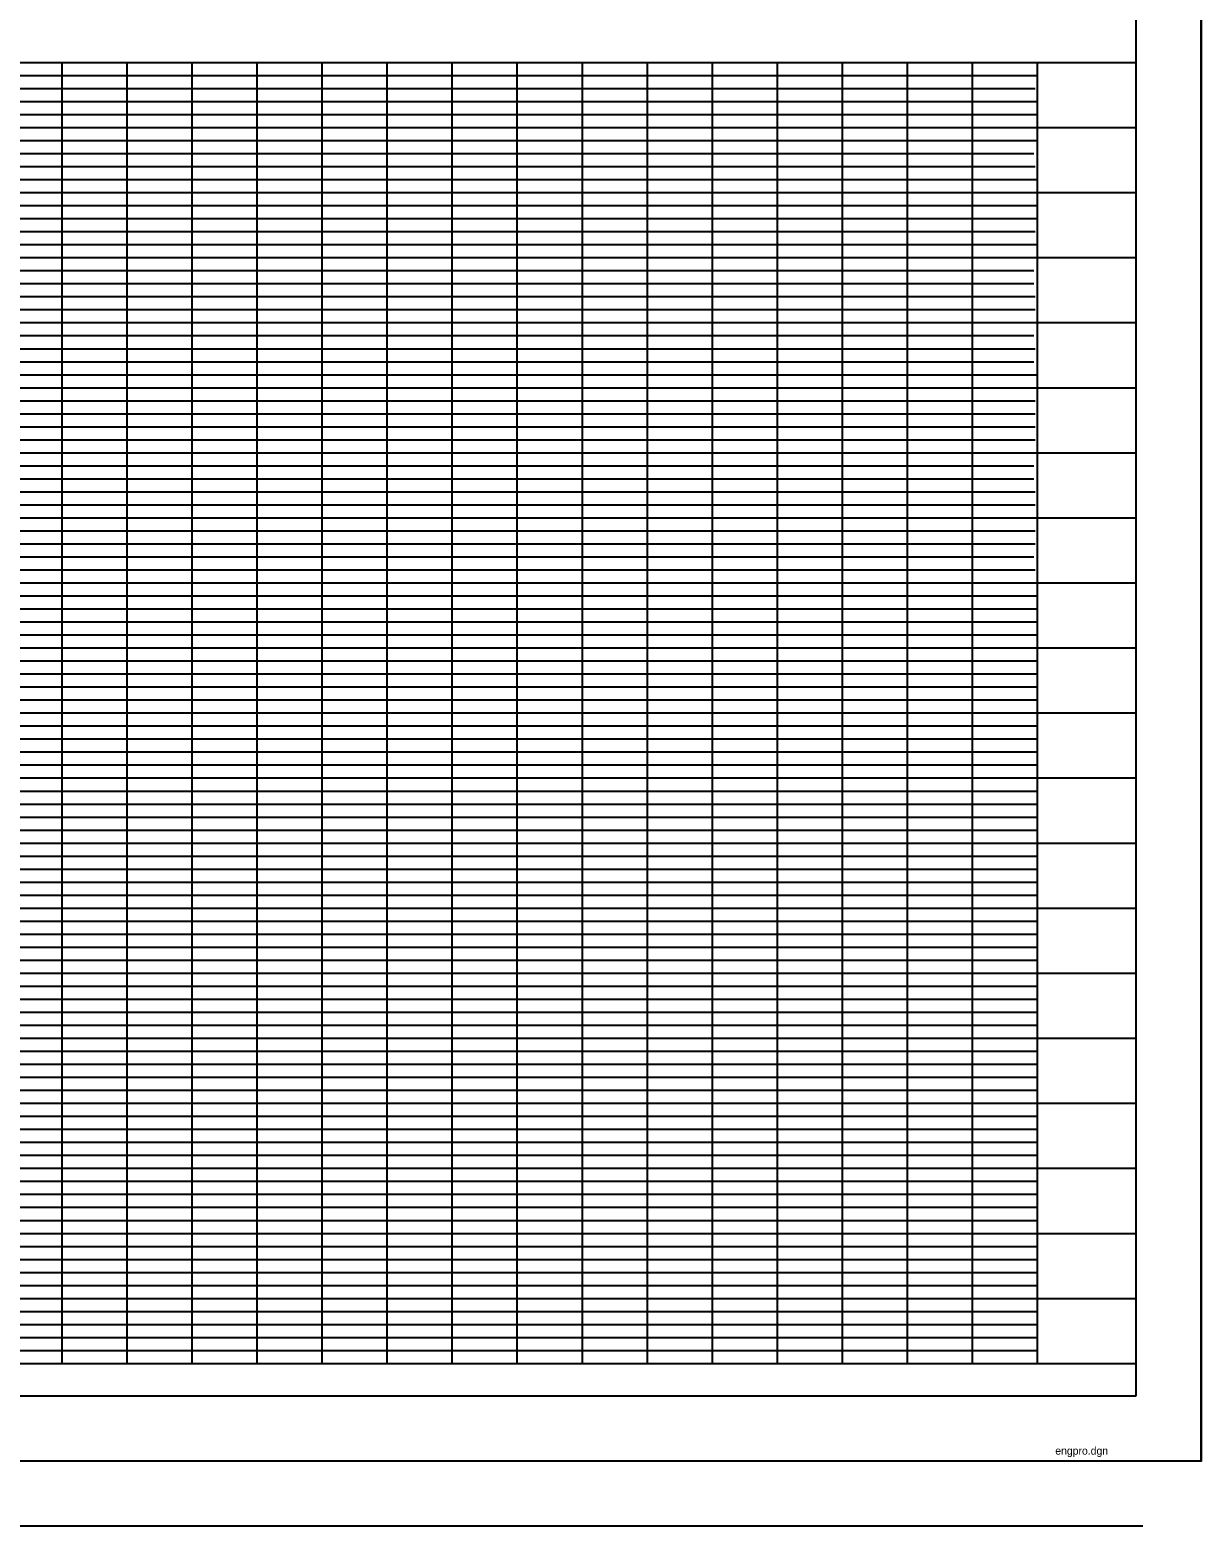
# Model space of a CAD drawing. Extents: x -184 to 1613, y -563 to 588.
# Drawn here: x 1163 to 1613, y -563 to 12 of the extents above; entities that cross this region are included whole.
import ezdxf

# ---------------------------------------------------------------- set-up
doc = ezdxf.new("R2010")
doc.units = 0
for name, color, linetype in [('RD_SHT_Bndy', 7, 'Continuous'), ('RD_SHT_IplotShp', 7, 'Continuous'), ('RD_SHT_MjGrid', 7, 'Continuous'), ('RD_SHT_MnGrid', 7, 'Continuous'), ('RD_SHT_Snap', 7, 'Continuous'), ('RD_SHT_SubGrid', 7, 'Continuous'), ('RD_SHT_TX', 7, 'Continuous')]:
    doc.layers.add(name, color=color, linetype=linetype)

msp = doc.modelspace()

# ---------------------------------------------------------------- linework, layer by layer
at = {"layer": 'RD_SHT_Bndy'}
for p, q in [((1588, -512.5), (1588, 537.5)), ((-87, 0), (1588, 0)), ((1550, 0), (1550, -500)), ((-87, -500), (1588, -500)), ((-87, -512.5), (1588, -512.5)), ((1590.65, -537.5), (-169.35, -537.5)), ((1590.65, -562.5), (-169.35, -562.5))]:
    msp.add_line(p, q, dxfattribs=at)
at = {"layer": 'RD_SHT_IplotShp'}
msp.add_lwpolyline([(-182.9, 562.5), (1613, 562.5), (1613, -537.5), (-182.9, -537.5)], close=True, dxfattribs=at)
at = {"layer": 'RD_SHT_MjGrid'}
for p, q in [((1200, 0), (1200, -500)), ((1250, 0), (1250, -500)), ((1300, 0), (1300, -500)), ((1350, 0), (1350, -500)), ((1400, 0), (1400, -500)), ((1450, 0), (1450, -500)), ((1500, 0), (1500, -500)), ((-87, -50), (1588, -50)), ((-87, -100), (1588, -100)), ((-87, -150), (1588, -150)), ((-87, -200), (1588, -200)), ((-87, -250), (1588, -250)), ((-87, -300), (1588, -300)), ((-87, -350), (1588, -350)), ((-87, -400), (1588, -400)), ((-87, -450), (1588, -450))]:
    msp.add_line(p, q, dxfattribs=at)
at = {"layer": 'RD_SHT_MnGrid'}
for p, q in [((1175, 0), (1175, -500)), ((1225, 0), (1225, -500)), ((1275, 0), (1275, -500)), ((1325, 0), (1325, -500)), ((1375, 0), (1375, -500)), ((1425, 0), (1425, -500)), ((1475, 0), (1475, -500)), ((1525, 0), (1525, -500)), ((-87, -25), (1588, -25)), ((-87, -75), (1588, -75)), ((-87, -125), (1588, -125)), ((-87, -175), (1588, -175)), ((-87, -225), (1588, -225)), ((-87, -275), (1588, -275)), ((-87, -325), (1588, -325)), ((-87, -375), (1588, -375)), ((-87, -425), (1588, -425)), ((-87, -475), (1588, -475))]:
    msp.add_line(p, q, dxfattribs=at)
at = {"layer": 'RD_SHT_Snap'}
msp.add_line((1613, -537.5), (1613, 562.5), dxfattribs=at)
at = {"layer": 'RD_SHT_SubGrid'}
for p, q in [((-49.95, -5), (1549.8, -5)), ((-49.95, -10), (1549.25, -10)), ((-49.95, -15), (1549.8, -15)), ((-49.9, -20), (1549.8, -20)), ((-49.95, -30), (1549.8, -30)), ((-49.95, -35), (1548.75, -35)), ((-49.95, -40), (1549.25, -40)), ((-49.95, -45), (1549.8, -45)), ((-49.95, -55), (1549.8, -55)), ((-49.95, -60), (1549.8, -60)), ((-49.95, -65), (1549.25, -65)), ((-49.95, -70), (1549.8, -70)), ((-49.95, -80), (1548.75, -80)), ((-49.95, -85), (1548.75, -85)), ((-49.95, -90), (1549.25, -90)), ((-49.95, -95), (1549.25, -95)), ((-49.95, -105), (1548.75, -105)), ((-49.95, -110), (1549.25, -110)), ((-49.95, -115), (1548.75, -115)), ((-49.9, -120), (1549.8, -120)), ((-49.95, -130), (1549.25, -130)), ((-49.95, -135), (1549.25, -135)), ((-49.95, -140), (1549.25, -140)), ((-49.95, -145), (1549.25, -145)), ((-49.85, -155), (1548.75, -155)), ((-49.85, -160), (1548.75, -160)), ((-49.9, -165), (1549.25, -165)), ((-49.9, -170), (1549.25, -170)), ((-49.95, -180), (1549.25, -180)), ((-49.95, -185), (1549.25, -185)), ((-49.95, -190), (1548.75, -190)), ((-49.95, -195), (1549.25, -195)), ((-49.95, -195), (1549.25, -195)), ((-49.95, -205), (1549.8, -205)), ((-49.95, -210), (1549.8, -210)), ((-49.95, -215), (1549.8, -215)), ((-49.95, -220), (1549.8, -220)), ((-49.95, -230), (1549.8, -230)), ((-49.95, -235), (1549.8, -235)), ((-49.95, -240), (1549.8, -240)), ((-49.95, -245), (1549.8, -245)), ((-49.95, -255), (1549.85, -255)), ((-49.95, -260), (1549.85, -260)), ((-49.95, -265), (1549.85, -265)), ((-49.95, -270), (1549.85, -270)), ((-49.95, -280), (1549.85, -280)), ((-49.95, -285), (1549.85, -285)), ((-49.95, -290), (1549.85, -290)), ((-49.95, -295), (1549.85, -295)), ((-49.95, -305), (1549.85, -305)), ((-49.95, -310), (1549.85, -310)), ((-49.95, -315), (1549.85, -315)), ((-49.95, -320), (1549.85, -320)), ((-49.95, -330), (1549.85, -330)), ((-49.9, -330), (1549.85, -330)), ((-49.95, -335), (1549.85, -335)), ((-49.9, -340), (1549.6, -340)), ((-49.9, -345), (1549.6, -345)), ((-49.9, -355), (1549.8, -355)), ((-49.95, -360), (1549.95, -360)), ((-49.95, -365), (1549.95, -365)), ((-49.9, -370), (1549.95, -370)), ((-49.95, -380), (1549.95, -380)), ((-49.95, -385), (1549.95, -385)), ((-49.95, -390), (1549.95, -390)), ((-49.9, -395), (1549.95, -395)), ((-49.95, -405), (1549.95, -405)), ((-49.95, -410), (1549.95, -410)), ((-49.95, -415), (1549.95, -415)), ((-49.95, -420), (1549.85, -420)), ((-49.9, -430), (1549.6, -430)), ((-49.95, -435), (1549.85, -435)), ((-49.95, -440), (1549.85, -440)), ((-49.95, -445), (1549.85, -445)), ((-49.95, -460), (1549.85, -460)), ((-49.85, -455), (1549.85, -455)), ((-49.95, -465), (1549.85, -465)), ((-49.95, -470), (1549.85, -470)), ((-49.85, -480), (1549.85, -480)), ((-49.85, -485), (1549.85, -485)), ((-49.85, -490), (1549.85, -490)), ((-49.85, -495), (1549.85, -495))]:
    msp.add_line(p, q, dxfattribs=at)

# ---------------------------------------------------------------- texts
at = {"layer": 'RD_SHT_TX'}
msp.add_text('engpro.dgn', height=3, dxfattribs=at).set_placement((1556.95, -535.05))

doc.saveas('drawing.dxf')
